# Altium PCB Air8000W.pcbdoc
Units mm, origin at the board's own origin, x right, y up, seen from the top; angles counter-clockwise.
Board outline 36.51 x 36.8 mm, 2 copper layers (Top Layer, Bottom Layer); 1 components, 0 nets, 104 pads, 0 vias.
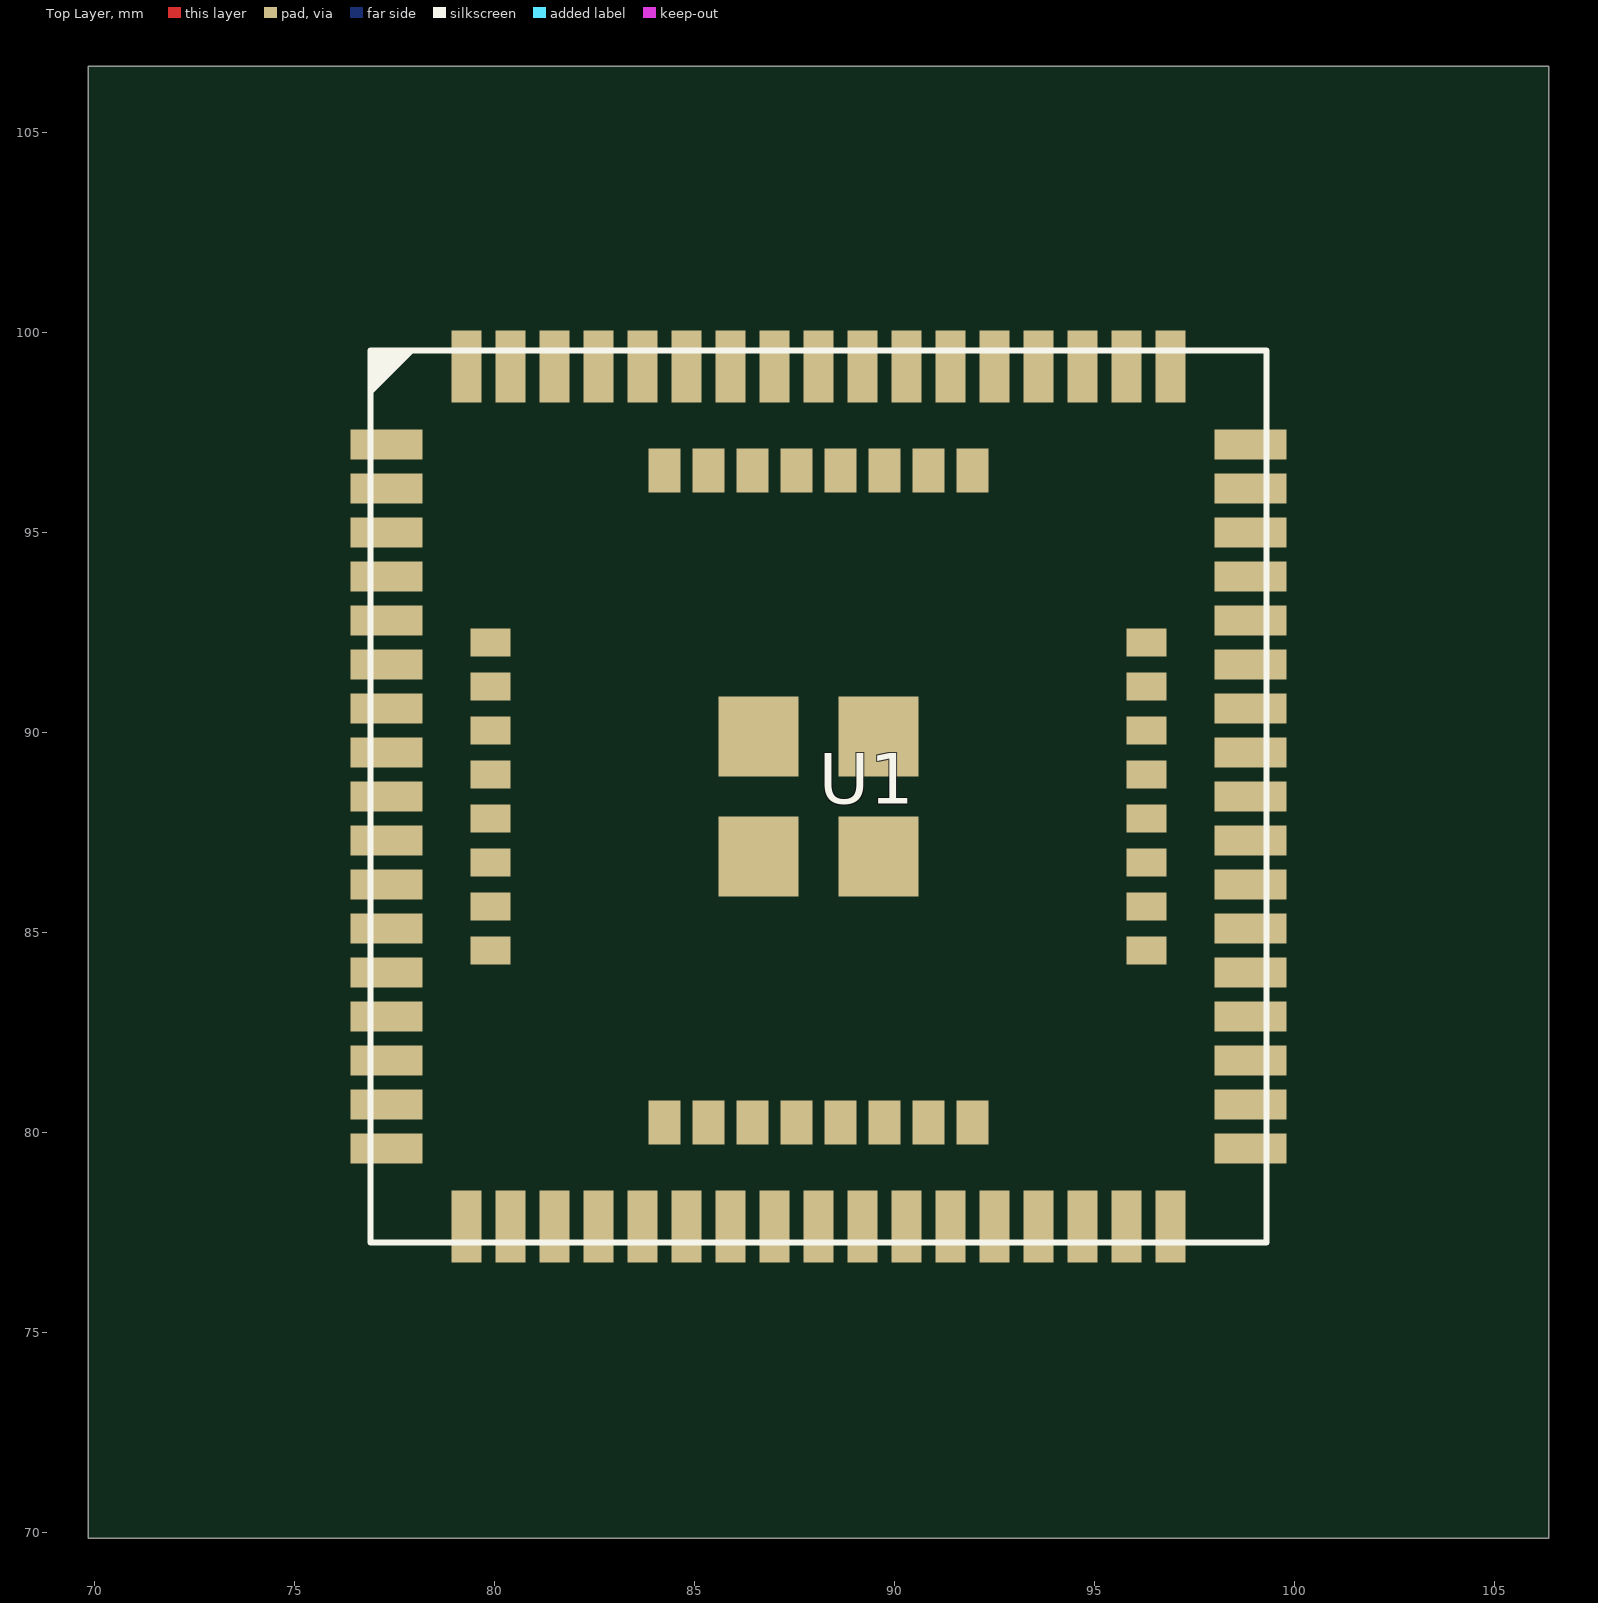
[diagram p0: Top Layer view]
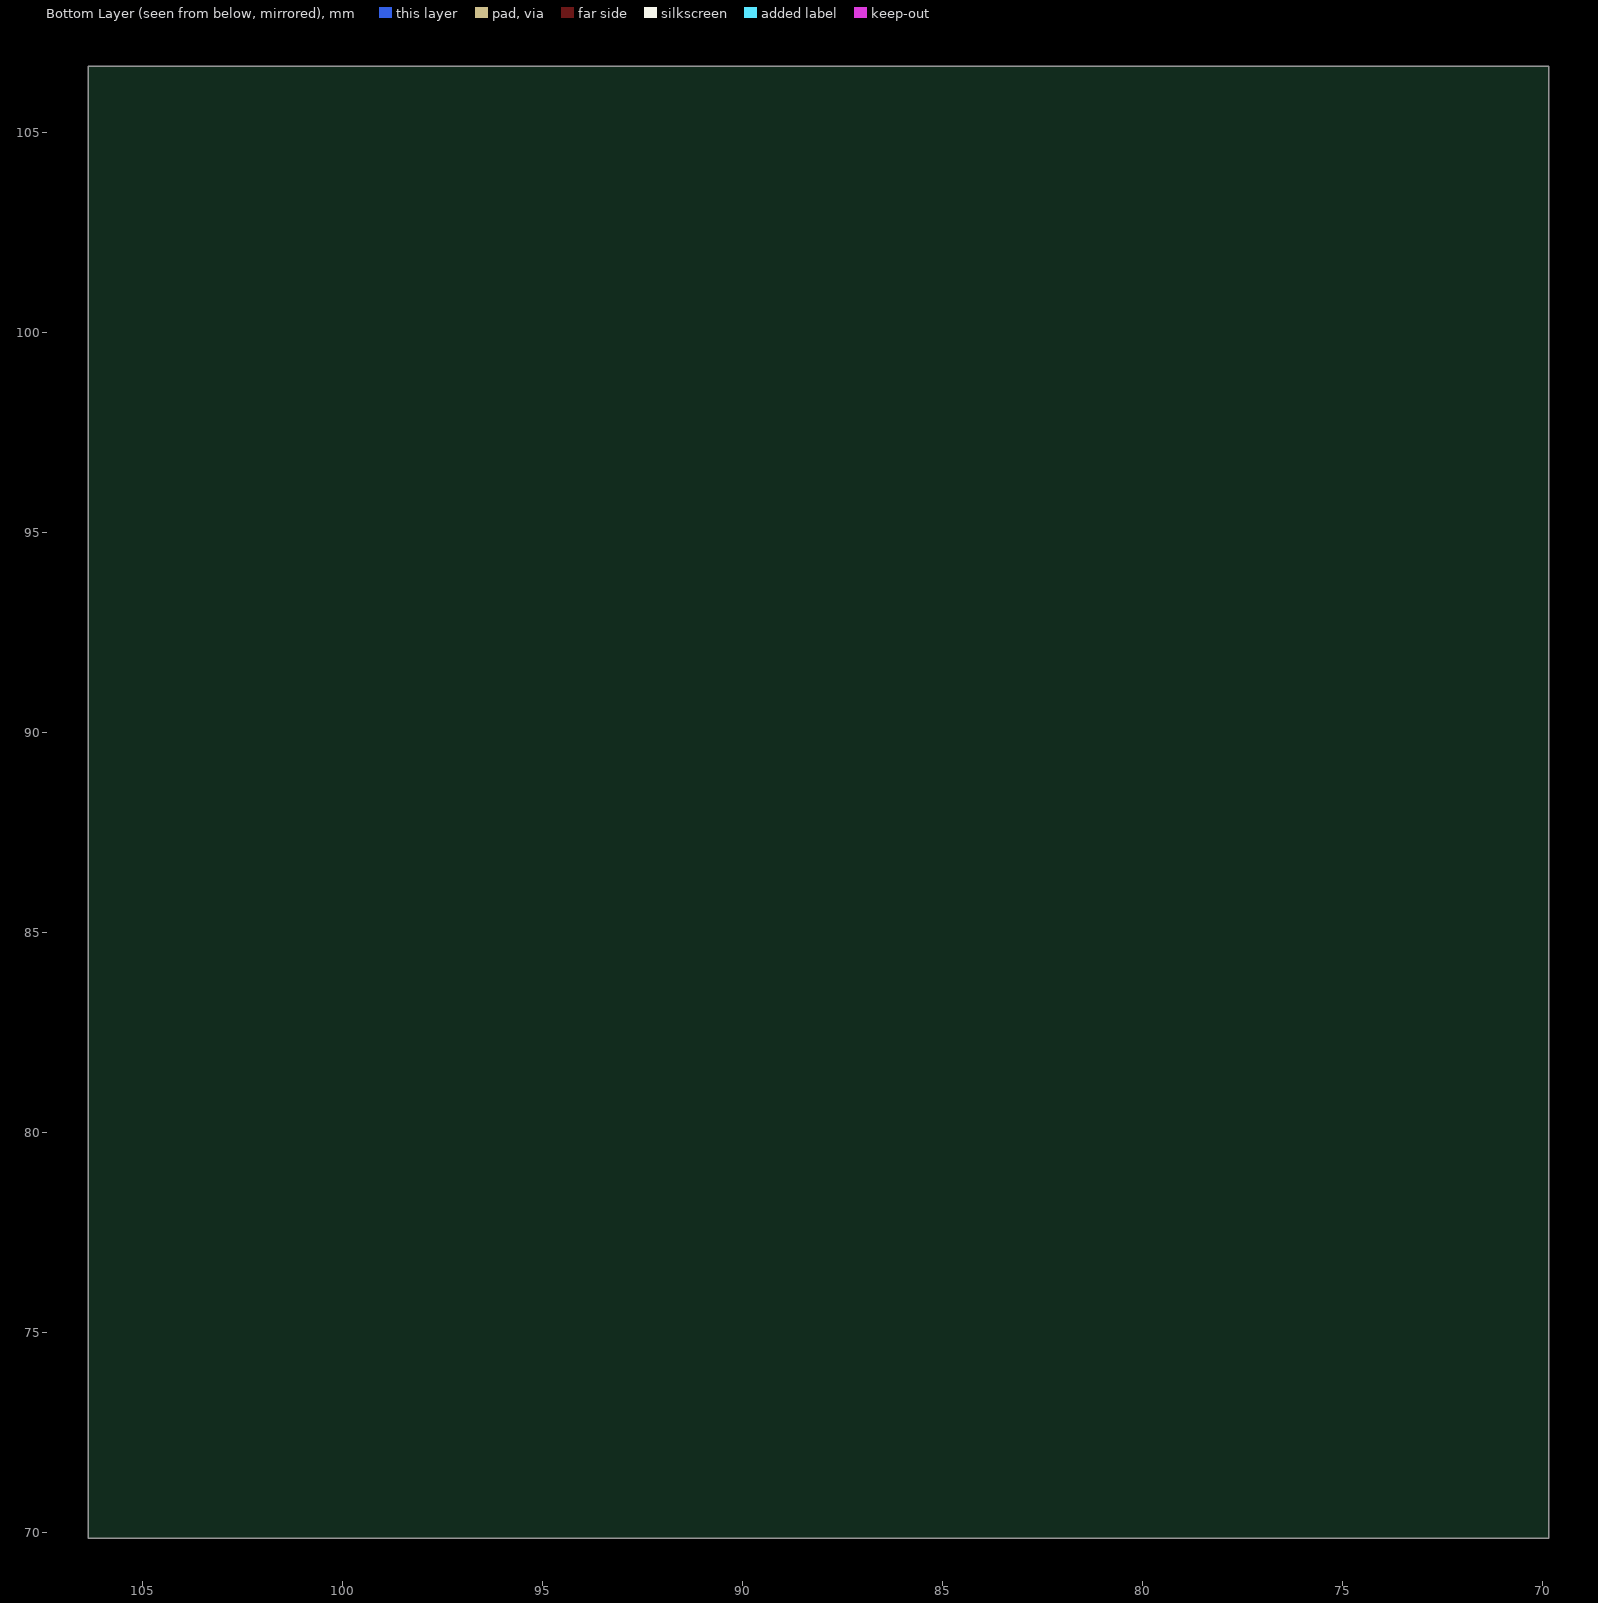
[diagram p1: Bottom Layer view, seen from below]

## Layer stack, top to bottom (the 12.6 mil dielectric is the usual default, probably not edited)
Top Layer: signal copper (thickness not stored)
Dielectric: dielectric 0.32, FR-4, Dk 4.8
Bottom Layer: signal copper (thickness not stored)

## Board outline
106.357,69.85 69.85,69.85 69.85,106.65 106.357,106.65

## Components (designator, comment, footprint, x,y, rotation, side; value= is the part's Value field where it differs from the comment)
U1 "AIR8000-PADS" AIR8000-PADS 88.106,88.401 r0 top

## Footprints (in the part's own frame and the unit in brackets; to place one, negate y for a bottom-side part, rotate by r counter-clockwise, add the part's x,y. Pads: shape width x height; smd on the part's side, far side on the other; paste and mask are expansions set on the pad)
AIR8000-PADS [mm]
  rect 1.8x0.75 smd: 1(-10.8,8.8) 2(-10.8,7.7) 3(-10.8,6.6) 4(-10.8,5.5) 5(-10.8,4.4) 6(-10.8,3.3) 7(-10.8,2.2) 8(-10.8,1.1) 9(-10.8,0) 10(-10.8,-1.1) 11(-10.8,-2.2) 12(-10.8,-3.3) 13(-10.8,-4.4) 14(-10.8,-5.5) 15(-10.8,-6.6) 16(-10.8,-7.7) 17(-10.8,-8.8) 35(10.8,-8.8) 36(10.8,-7.7) 37(10.8,-6.6) 38(10.8,-5.5) 39(10.8,-4.4) 40(10.8,-3.3) 41(10.8,-2.2) 42(10.8,-1.1) 43(10.8,0) 44(10.8,1.1) 45(10.8,2.2) 46(10.8,3.3) 47(10.8,4.4) 48(10.8,5.5) 49(10.8,6.6) 50(10.8,7.7) 51(10.8,8.8)
  rect 0.75x1.8 smd: 18(-8.8,-10.75) 19(-7.7,-10.75) 20(-6.6,-10.75) 21(-5.5,-10.75) 22(-4.4,-10.75) 23(-3.3,-10.75) 24(-2.2,-10.75) 25(-1.1,-10.75) 26(0,-10.75) 27(1.1,-10.75) 28(2.2,-10.75) 29(3.3,-10.75) 30(4.4,-10.75) 31(5.5,-10.75) 32(6.6,-10.75) 33(7.7,-10.75) 34(8.8,-10.75) 52(8.8,10.75) 53(7.7,10.75) 54(6.6,10.75) 55(5.5,10.75) 56(4.4,10.75) 57(3.3,10.75) 58(2.2,10.75) 59(1.1,10.75) 60(0,10.75) 61(-1.1,10.75) 62(-2.2,10.75) 63(-3.3,10.75) 64(-4.4,10.75) 65(-5.5,10.75) 66(-6.6,10.75) 67(-7.7,10.75) 68(-8.8,10.75)
  rect 1x0.7 smd: 69(-8.2,3.85) 70(-8.2,2.75) 71(-8.2,1.65) 72(-8.2,0.55) 73(-8.2,-0.55) 74(-8.2,-1.65) 75(-8.2,-2.75) 76(-8.2,-3.85) 85(8.2,-3.85) 86(8.2,-2.75) 87(8.2,-1.65) 88(8.2,-0.55) 89(8.2,0.55) 90(8.2,1.65) 91(8.2,2.75) 92(8.2,3.85)
  rect 0.8x1.1 smd: 77(-3.85,-8.15) 78(-2.75,-8.15) 79(-1.65,-8.15) 80(-0.55,-8.15) 81(0.55,-8.15) 82(1.65,-8.15) 83(2.75,-8.15) 84(3.85,-8.15) 93(3.85,8.15) 94(2.75,8.15) 95(1.65,8.15) 96(0.55,8.15) 97(-0.55,8.15) 98(-1.65,8.15) 99(-2.75,8.15) 100(-3.85,8.15)
  rect 2x2 smd: 101(-1.5,1.5) 102(-1.5,-1.5) 103(1.5,-1.5) 104(1.5,1.5)
  silkscreen extent -11.22,-11.15 11.2,11.15

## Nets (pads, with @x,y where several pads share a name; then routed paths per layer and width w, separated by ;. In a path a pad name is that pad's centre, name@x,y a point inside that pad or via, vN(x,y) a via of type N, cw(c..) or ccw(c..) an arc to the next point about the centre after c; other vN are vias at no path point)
pads on no net: U1.1 U1.2 U1.3 U1.4 U1.5 U1.6 U1.7 U1.8 U1.9 U1.10 U1.11 U1.12 U1.13 U1.14 U1.15 U1.16 U1.17 U1.18 U1.19 U1.20 U1.21 U1.22 U1.23 U1.24 U1.25 U1.26 U1.27 U1.28 U1.29 U1.30 U1.31 U1.32 U1.33 U1.34 U1.35 U1.36 U1.37 U1.38 U1.39 U1.40 U1.41 U1.42 U1.43 U1.44 U1.45 U1.46 U1.47 U1.48 U1.49 U1.50 U1.51 U1.52 U1.53 U1.54 U1.55 U1.56 U1.57 U1.58 U1.59 U1.60 U1.61 U1.62 U1.63 U1.64 U1.65 U1.66 U1.67 U1.68 U1.69 U1.70 U1.71 U1.72 U1.73 U1.74 U1.75 U1.76 U1.77 U1.78 U1.79 U1.80 U1.81 U1.82 U1.83 U1.84 U1.85 U1.86 U1.87 U1.88 U1.89 U1.90 U1.91 U1.92 U1.93 U1.94 U1.95 U1.96 U1.97 U1.98 U1.99 U1.100 U1.101 U1.102 U1.103 U1.104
